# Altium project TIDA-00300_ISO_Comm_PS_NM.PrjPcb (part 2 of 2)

## Sheet TIDA-00300_ISO_Comm_PS_NM_Pg6.SchDoc
size 431 x 279 mm; Date: Not shown in title block; ApprovedBy: Not shown in title block; CheckedBy: Not shown in title block; Author: Not shown in title block; CompanyName: Not shown in title block; DrawnBy: Sreenivasa; Engineer: Not shown in title block; Organization: Not shown in title block; Address1: Not shown in title block; Address2: Not shown in title block; Address3: Not shown in title block; Address4: Not shown in title block; DocumentNumber: 1; Revision: Use project parameter SCH_Rev; SheetNumber: 6; SheetTotal: 7; PageSetup: Record=PageOptions¦CenterHorizontal=True¦CenterVertical=True¦PrintScale=0.62¦XCorrection=1.00¦YCorrection=1.00¦PrintKind=0¦BorderSize=5000000¦LeftOffset=0¦BottomOffset=0¦Orientation=2¦PaperLength=1000¦PaperWidth=1000¦Scale=100¦PaperSource=15¦PrintQuality=600¦MediaType=1¦DitherType=10¦PrintScaleMode=1¦PaperKind=Letter
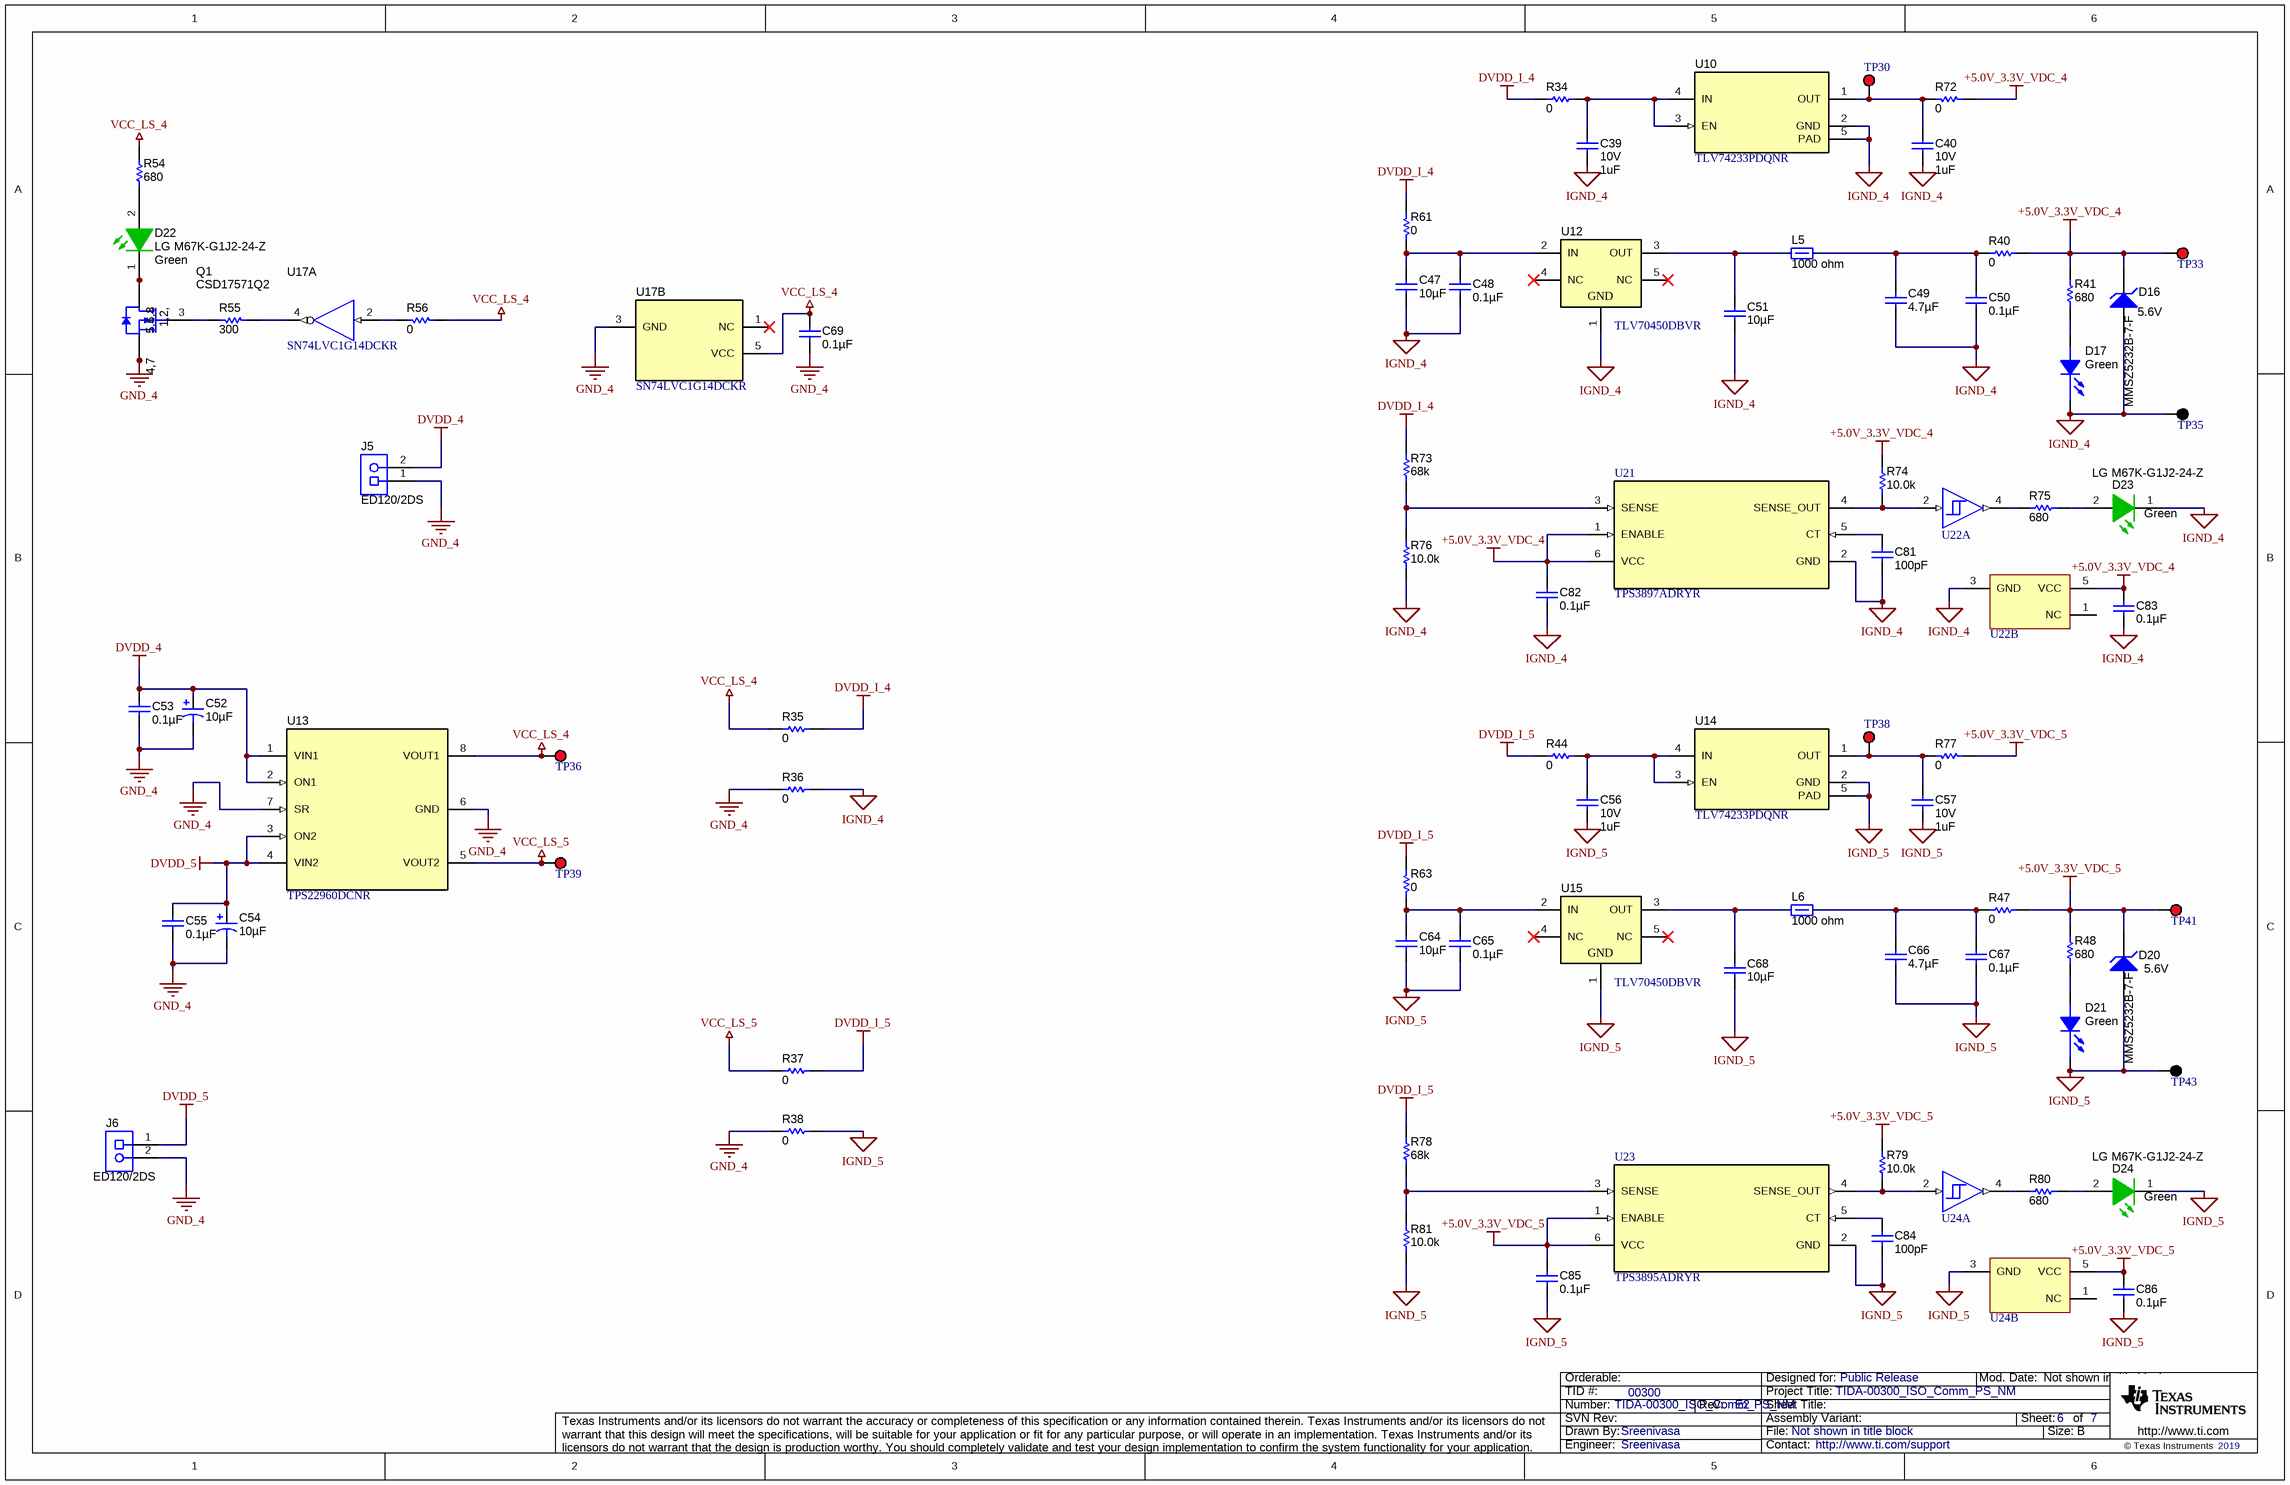
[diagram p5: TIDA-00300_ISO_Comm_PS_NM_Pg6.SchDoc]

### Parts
C39  VDC_V: 10V  ValueDisplayed: 1uF  [0402]  (hidden comment: GRM155R61A105KE15D)
C40  VDC_V: 10V  ValueDisplayed: 1uF  [0402]  (hidden comment: GRM155R61A105KE15D)
C47  ValueDisplayed: 10µF  [1210]
C48  ValueDisplayed: 0.1µF  [0603]
C49  ValueDisplayed: 4.7µF  [0805_HV]
C50  ValueDisplayed: 0.1µF  [0603]
C51  ValueDisplayed: 10µF  [1210]
C52  ValueDisplayed: 10µF  [3528-21]  (hidden comment: T491B106K016AT)
C53  ValueDisplayed: 0.1µF  [0603]
C54  ValueDisplayed: 10µF  [3528-21]  (hidden comment: T491B106K016AT)
C55  ValueDisplayed: 0.1µF  [0603]
C56  VDC_V: 10V  ValueDisplayed: 1uF  [0402]  (hidden comment: GRM155R61A105KE15D)
C57  VDC_V: 10V  ValueDisplayed: 1uF  [0402]  (hidden comment: GRM155R61A105KE15D)
C64  ValueDisplayed: 10µF  [1210]
C65  ValueDisplayed: 0.1µF  [0603]
C66  ValueDisplayed: 4.7µF  [0805_HV]
C67  ValueDisplayed: 0.1µF  [0603]
C68  ValueDisplayed: 10µF  [1210]
C69  ValueDisplayed: 0.1µF  [0603]  (hidden comment: GMK107BJ104KAHT)
C81  ValueDisplayed: 100pF  [0402]  (hidden comment: 0402YC101KAT2A)
C82  ValueDisplayed: 0.1µF  [0603]
C83  ValueDisplayed: 0.1µF  [0603]
C84  ValueDisplayed: 100pF  [0402]  (hidden comment: 0402YC101KAT2A)
C85  ValueDisplayed: 0.1µF  [0603]
C86  ValueDisplayed: 0.1µF  [0603]
D16  MMSZ5232B-7-F  value 5.6V  [SOD-123]
D17  value Green  [LED0603AA]
D20  MMSZ5232B-7-F  value 5.6V  [SOD-123]
D21  value Green  [LED0603AA]
D22  LG M67K-G1J2-24-Z  value Green  [LG_M67K_Green]
D23  LG M67K-G1J2-24-Z  value Green  [LG_M67K_Green]
D24  LG M67K-G1J2-24-Z  value Green  [LG_M67K_Green]
J5  ED120/2DS  [CONN_ED120-2DS]
J6  ED120/2DS  [CONN_ED120-2DS]
L5  value 1000 ohm  [MMZ1608_095]  (hidden comment: MMZ1608B102CTA00)
L6  value 1000 ohm  [MMZ1608_095]  (hidden comment: MMZ1608B102CTA00)
Q1  CSD17571Q2  [DQK0006C]
R34  ValueDisplayed: 0  [0402S]  (hidden comment: RC0402JR-070RL)
R35  ValueDisplayed: 0  [0603]  (hidden comment: CRCW06030000Z0EA)
R36  ValueDisplayed: 0  [0603]  (hidden comment: CRCW06030000Z0EA)
R37  ValueDisplayed: 0  [0603]  (hidden comment: CRCW06030000Z0EA)
R38  ValueDisplayed: 0  [0603]  (hidden comment: CRCW06030000Z0EA)
R40  value 0  [0603]  (hidden comment: CRCW06030000Z0EA)
R41  ValueDisplayed: 680  [0603]  (hidden comment: RC0603FR-07680RL)
R44  ValueDisplayed: 0  [0402S]  (hidden comment: RC0402JR-070RL)
R47  value 0  [0603]  (hidden comment: CRCW06030000Z0EA)
R48  ValueDisplayed: 680  [0603]  (hidden comment: RC0603FR-07680RL)
R54  ValueDisplayed: 680  [0603]  (hidden comment: RC0603FR-07680RL)
R55  ValueDisplayed: 300  [0603]  (hidden comment: CRCW0603300RJNEA)
R56  ValueDisplayed: 0  [0603]  (hidden comment: RMCF0603ZT0R00)
R61  ValueDisplayed: 0  [0603]  (hidden comment: CRCW06030000Z0EA)
R63  ValueDisplayed: 0  [0603]  (hidden comment: CRCW06030000Z0EA)
R72  ValueDisplayed: 0  [0603]  (hidden comment: CRCW06030000Z0EA)
R73  ValueDisplayed: 68k  [0402]  (hidden comment: CRCW040268K0JNED)
R74  ValueDisplayed: 10.0k  [0402]  (hidden comment: CRCW040210K0FKED)
R75  ValueDisplayed: 680  [0603]  (hidden comment: RC0603FR-07680RL)
R76  ValueDisplayed: 10.0k  [0402]  (hidden comment: CRCW040210K0FKED)
R77  ValueDisplayed: 0  [0603]  (hidden comment: CRCW06030000Z0EA)
R78  ValueDisplayed: 68k  [0402]  (hidden comment: CRCW040268K0JNED)
R79  ValueDisplayed: 10.0k  [0402]  (hidden comment: CRCW040210K0FKED)
R80  ValueDisplayed: 680  [0603]  (hidden comment: RC0603FR-07680RL)
R81  ValueDisplayed: 10.0k  [0402]  (hidden comment: CRCW040210K0FKED)
TP30  5000  [Keystone5000]  (value not drawn)
TP33  5000  [Keystone5000]  (value not drawn)
TP35  5001  [Keystone5001]  (value not drawn)
TP36  5000  [Keystone5000]  (value not drawn)
TP38  5000  [Keystone5000]  (value not drawn)
TP39  5000  [Keystone5000]  (value not drawn)
TP41  5000  [Keystone5000]  (value not drawn)
TP43  5001  [Keystone5001]  (value not drawn)
U10  TLV74233PDQNR  [DQN0004A]
U12  TLV70450DBVR  [DBV0005A_N]
U13  TPS22960DCNR  [DCN0008A_N]
U14  TLV74233PDQNR  [DQN0004A]
U15  TLV70450DBVR  [DBV0005A_N]
U17  SN74LVC1G14DCKR  [DCK0005A_N]  (parts A,B of 2)
U21  TPS3897ADRYR  [DRY0006A]
U22  SN74LVC1G17DCKR  [DCK0005A_N]  (value not drawn)  (parts A,B of 2)
U23  TPS3895ADRYR  [DRY0006A]
U24  SN74LVC1G17DCKR  [DCK0005A_N]  (value not drawn)  (parts A,B of 2)

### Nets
+5.0V_3.3V_VDC_4: C82.1 C83.1 D16.1(K) R40.2 R41.2 R72.1 R74.1 TP33.1 U21.1(ENABLE) U21.6(VCC) U22.5(VCC)
+5.0V_3.3V_VDC_5: C85.1 C86.1 D20.1(K) R47.2 R48.2 R77.1 R79.1 TP41.1 U23.1(ENABLE) U23.6(VCC) U24.5(VCC)
DVDD_4: C52.1(+) C53.2 J5.2 U13.1(VIN1) U13.2(ON1)
DVDD_5: C54.1(+) C55.2 J6.1 U13.3(ON2) U13.4(VIN2)
DVDD_I_4: R34.1 R35.1 R61.2 R73.2
DVDD_I_5: R37.1 R44.1 R63.2 R78.2
GND_4: C52.2(-) C53.1 C54.2(-) C55.1 C69.2 J5.1 J6.2 Q1.4(S) Q1.7(S) R36.2 R38.2 U13.6(GND) U13.7(SR) U17.3(GND)
IGND_4: C39.2 C40.2 C47.1 C48.2 C49.1 C50.2 C51.1 C81.2 C82.2 C83.2 D16.2(A) D17.1(C) D23.1(K) R36.1 R76.1 TP35.1 U10.2(GND) U10.5(PAD) U12.1(GND) U21.2(GND) U22.3(GND)
IGND_5: C56.2 C57.2 C64.1 C65.2 C66.1 C67.2 C68.1 C84.2 C85.2 C86.2 D20.2(A) D21.1(C) D24.1(K) R38.1 R81.1 TP43.1 U14.2(GND) U14.5(PAD) U15.1(GND) U23.2(GND) U24.3(GND)
VCC_LS_4: C69.1 R35.2 R54.2 R56.1 TP36.1 U13.8(VOUT1) U17.5(VCC)
VCC_LS_5: R37.2 TP39.1 U13.5(VOUT2)
NetC39_1: C39.1 R34.2 U10.3(EN) U10.4(IN)
NetC40_1: C40.1 R72.2 TP30.1 U10.1(OUT)
NetC47_2: C47.2 C48.1 R61.1 U12.2(IN)
NetC49_2: C49.2 C50.1 L5.2 R40.1
NetC51_2: C51.2 L5.1 U12.3(OUT)
NetC56_1: C56.1 R44.2 U14.3(EN) U14.4(IN)
NetC57_1: C57.1 R77.2 TP38.1 U14.1(OUT)
NetC64_2: C64.2 C65.1 R63.1 U15.2(IN)
NetC66_2: C66.2 C67.1 L6.2 R47.1
NetC68_2: C68.2 L6.1 U15.3(OUT)
NetC81_1: C81.1 U21.5(CT)
NetC84_1: C84.1 U23.5(CT)
NetD17_2: D17.2(A) R41.1
NetD21_2: D21.2(A) R48.1
NetD22_1: D22.1(K) Q1.1(D) Q1.2(D) Q1.5(D) Q1.6(D) Q1.8(D)
NetD22_2: D22.2(A) R54.1
NetD23_2: D23.2(A) R75.2
NetD24_2: D24.2(A) R80.2
NetQ1_3: Q1.3(G) R55.1
NetR55_2: R55.2 U17.4(Y)
NetR56_2: R56.2 U17.2(A)
NetR73_1: R73.1 R76.2 U21.3(SENSE)
NetR74_2: R74.2 U21.4(SENSE_OUT) U22.2(A)
NetR75_1: R75.1 U22.4(Y)
NetR78_1: R78.1 R81.2 U23.3(SENSE)
NetR79_2: R79.2 U23.4(SENSE_OUT) U24.2(A)
NetR80_1: R80.1 U24.4(Y)

Not connected (* = marked no-connect by the designer): U12 4(NC)* 5(NC)*; U15 4(NC)* 5(NC)*; U17 1(NC)*; U22 1(NC); U24 1(NC)

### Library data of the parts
C39 C40 C56 C57 = CMP-0006563-2: CAP, CERM, 1 uF, 10 V, +/- 10%, X5R, 0402; Manufacturer: MuRata; TaMin_C: -55°C; Polarized: N; SizeAreaWB_mm2: 3; Value1: Unknown; U/M: EA; Value: 1uF; TaMax_C: 85°C; SizeZ_mm: 0.6; SizeX_mm: 1; SizeY_mm: 0.5; Cap_F: 1µF; AEC Category: Q200
C47 C51 C64 C68 = GMK325AB7106MM-T: CAP, CERM, 10uF, 35V, +/-20%, X7R, 1210; Manufacturer: Taiyo Yuden; Polarized: N; CompType: Capacitor; U/M: EA; Cap_F: 0.00001; Tolerance_%: 20; Value1: Unknown; VDC_V: 35; TaMin_C: -55; TaMax_C: 125
C48 C50 C53 C55 C65 C67 C82 C83 C85 C86 = C0603C104K5RACTU: CAP, CERM, 0.1uF, 50V, +/-10%, X7R, 0603; Manufacturer: Kemet; Polarized: N; CompType: Capacitor; U/M: EA; Cap_F: 0.0000001; Tolerance_%: 10; Value1: Unknown; VDC_V: 50; TaMin_C: -55; TaMax_C: 125
C49 C66 = C2012X5R1H475K125AB: 4.7µF ±10% 50V X5R Ceramic Capacitor -55°C ~ 85°C; PartNumber: GRM21BR61H475KE51L; Manufacturer: TDK; Polarized: N; Value: 4.7uF; U/M: EA; Cap_F: 0.0000047; Tolerance_%: 10; Value1: Unknown; VDC_V: 50; TaMin_C: -55; TaMax_C: 85; Cap_Case: 0805
C52 C54 = 293D106X9016B2TE3: CAP, TA, 10 µF, 16 V, +/- 10%, 2 ohm, SMD; Manufacturer: Vishay-Sprague; Polarized: Y; CompType: Capacitor; Value: 10uF; U/M: EA; Cap_F: 0.00001; Tolerance_%: 10; Value1: 2 ohm; VDC_V: 16; Value2: 16V; ESR_ohm: 2; IRMS_A: 0.21; TaMin_C: -55; TaMax_C: 125; Cap_Case: B
C69 = 06033C104JAT2A: 0.1µF ±10% 35V Ceramic Capacitor X5R 0603; Manufacturer: Taiyo Yuden; Polarized: N; Value: 0.1uF; U/M: EA; Cap_F: 0.0000001; Tolerance_%: 5; ESR_ohm: 0.05; Value1: 0.05 ohm; VDC_V: 25; Value2: 25V; TempCo: X7R; TaMin_C: -55; TaMax_C: 125; SizeArea_mm2: 1.28; SizeAreaWB_mm2: 4.68; SizeX_mm: 1.6; SizeY_mm: 0.8; SizeZ_mm: 1; AEC Category: Q200
C81 C84 = 0402YC101KAT2A: CAP, CERM, 100 pF, 16 V,+/- 10%, X7R, 0402; Manufacturer: AVX; Polarized: N; CompType: Capacitor; Value: 100pF; U/M: EA; Cap_F: 0.0000000001; Tolerance_%: 10; VDC_V: 16; Value2: 16V; TaMin_C: -55; TaMax_C: 125; SizeArea_mm2: 0.5; SizeAreaWB_mm2: 3; SizeX_mm: 1; SizeZ_mm: 0.6; AEC Category: Q200
D16 D20 = MMSZ5232B-7-F: Diode, Zener, 5.6 V, 500 mW, SOD-123; Manufacturer: Diodes Inc.; SymbolCreator: a0412235; U/M: EA; Power_W: 0.5; Vz_V: 5.6; Value1: 0.5W; RJA_CperW: 350; AEC Category: Q101
D17 D21 = LED_LG L29K-G2J1-24-Z: LED SmartLED Green 570NM; Manufacturer: OSRAM; SymbolCreator: x0120606
D22-D24 = LG M67K-G1J2-24-Z: LED, Green, SMD; Manufacturer: OSRAM; SymbolCreator: Altium; Type: AlInGaP; Vf_V: 1.8; Value2: 1.8V; Io_A: 0.002; Vr_V: 12; Tjmax_C: 125; Value1: W; Angle: 120; U/M: EA
J5 J6 = ED120/2DS: TERMINAL BLOCK 5.08MM VERT 2POS, TH; Manufacturer: On-Shore Technology; SymbolCreator: a0412235; U/M: EA
L5 L6 = MMZ1608B102CTA00: Ferrite Bead, 1000 ohm @ 100 MHz, 0.3 A, 0603; Manufacturer: TDK; Imax_A: 0.3; DCR_ohm: 0.6; Value1: 0.6 ohm; Value2: 0.3A; ZTyp@100MHz_Ohm: 1000
Q1 = CSD17571Q2: MOSFET, N-CH, 30 V, 22 A, DQK0006C (WSON-6); Manufacturer: Texas Instruments; Alternate Manufacturer: None; U/M: EA; ChType: N; Value: 30V; VdsMax_V: 30; Value1: 0.029 ohm; Rdson45_ohm: 0.029; Value2: 2.4 nC; QgTyp_nC: 2.4; Vgs_V: 20; IdsMax_A: 22; SizeAreaWB_mm2: 9; SizeArea_mm2: 4; SizeX_mm: 2; SizeZ_mm: 0.8; AEC Category: Q101
R34 R44 = CMP-0027004-2: RES, 0, 5%, 0.063 W, 0402; Manufacturer: Yageo America; Power_W: 63mW; TempCo: 200 ppm/C; Value_Code: 0000; U/M: EA; Value: 0; EIA_Code: E24; SizeX_mm: 1; SizeY_mm: 0.5; SizeZ_mm: 0.6; Value2: 0.063W; VDC_V: 50V; AEC Category: Q200
R35-R38 R61 R63 R72 R77 = CRCW06030000Z0EA: RES, 0, 5%, 0.1 W, 0603; Manufacturer: Vishay-Dale; CompType: Resistor; Value: 0; Value_Code: 0000; Tolerance_%: 5; Power_W: 0.1; Value2: 0.1W; VDC_V: 75; TempCo: 200 ppm/C; EIA_Code: E24; U/M: EA
R40 R47 = CRCW06030000Z0EA: RES, 0 ohm, 5%, 0.1W, 0603; Manufacturer: Vishay-Dale; CompType: Resistor; Value_Code: 0000; Tolerance_%: 5; Power_W: 0.1; VDC_V: 75; TempCo: 200 ppm/C; EIA_Code: E24; U/M: EA
R41 R48 R54 R75 R80 = RC0603FR-07680RL: RES, 680, 1%, 0.1 W, 0603; Manufacturer: Yageo America; CompType: Resistor; Value: 680; Value_Code: 680R; Tolerance_%: 1; Power_W: 0.1; Value2: 0.1W; VDC_V: 150; TempCo: 200 ppm/C; SizeArea_mm2: 1.28; SizeX_mm: 1.6; SizeY_mm: 0.8; U/M: EA; AEC Category: Q200; Green_Lifecycle: Active; Green_REACh: Passed
R55 = CRCW0603300RJNEA: RES, 300, 5%, 0.1 W, 0603; Manufacturer: Vishay-Dale; CompType: Resistor; Value: 300; Value_Code: 300R; Tolerance_%: 5; Power_W: 0.1; Value2: 0.1W; VDC_V: 75; TempCo: 200 ppm/C; SizeArea_mm2: 1.28; SizeX_mm: 1.6; SizeY_mm: 0.8; SizeZ_mm: 1; EIA_Code: E24; U/M: EA; AEC Category: Q200
R56 = RMCF0603ZT0R00: RES, 0, 1%, 0.1 W, AEC-Q200 Grade 0, 0603; Manufacturer: Stackpole Electronics Inc; CompType: Resistor; Value: 0; Tolerance_%: 1; Power_W: 0.1; Value2: 0.1W; TempCo: ppm/C; SizeArea_mm2: 1.28; SizeX_mm: 1.6; SizeY_mm: 0.8; U/M: EA; AEC Category: Q200; AEC Qualified: Y
R73 R78 = CRCW040268K0JNED: RES, 68 k, 5%, 0.063 W, 0402; Manufacturer: Vishay-Dale; CompType: Resistor; Value: 68k; Res_ohm: 68000; Value_Code: 68k0; Tolerance_%: 5; Power_W: 0.063; Value2: 0.063W; VDC_V: 50; TempCo: 200 ppm/C; SizeArea_mm2: 0.5; SizeX_mm: 1; SizeZ_mm: 0.6; EIA_Code: E24; U/M: EA; AEC Category: Q200
R74 R76 R79 R81 = CRCW040210K0FKED: RES, 10.0 k, 1%, 0.063 W, 0402; Manufacturer: Vishay-Dale; CompType: Resistor; Value: 10.0k; Res_ohm: 10000; Value_Code: 10k0; Tolerance_%: 1; Power_W: 0.063; Value2: 0.063W; VDC_V: 50; TempCo: 100 ppm/C; SizeArea_mm2: 0.5; SizeZ_mm: 0.6; EIA_Code: E96; U/M: EA; AEC Category: Q200; Green_Lifecycle: Active; Green_REACh: Passed
TP30 TP33 TP36 TP38 TP39 TP41 = 5000: Test Point, Miniature, Red, TH; Manufacturer: Keystone; CompType: Test Point Loop; ContactFinish: Silver; Green_Lifecycle: Active; Green_REACh: Passed
TP35 TP43 = 5001: Test Point, Miniature, Black, TH; Manufacturer: Keystone; CompType: Test Point Loop; ContactFinish: Silver; Green_Lifecycle: Active; Green_REACh: Passed
U10 U14 = CMP-0079101-1: 200-mA, Small Size, Low-Dropout Linear Voltage Regulator, DQN0004A (X2SON-4); Alternate Manufacturer: Texas Instruments; SizeAreaWB_mm2: 4; SizeZ_mm: 0.4; SizeX_mm: 1; CompType: IC; AEC Qualified: N; AEC Category: Q200
U12 U15 = TLV70450DBVR: Single Output LDO, 150 mA, Fixed 5 V Output, 2.5 to 24 V Input, with Ultra-Low IQ, 5-pin SOT-23 (DBV), -40 to 125 degC, Green (RoHS & no Sb/Br); Manufacturer: Texas Instruments; Alternate PartNumber: Equivalent; Accuracy(%): 2; Fixed Output Options(V): 5; Iout(Max)(A): 0.15; Iq(Typ)(mA): 0.003; SubFamily: Single Channel LDO; Vdo(Typ)(mV): 400; Vin(Max)(V): 24; Vin(Min)(V): 2.5
U13 = CMP-0066654-1: 5.5V, 0.5A, 435mΩ, 2-Channel Load Switch with Quick Output Discharge, DCN0008A (SOT-23-8); Alternate Manufacturer: Texas Instruments; SizeAreaWB_mm2: 15.21; U/M: EA; SizeZ_mm: 1.1; SizeX_mm: 2.9; SizeArea_mm2: 8.41; CompType: IC
U17 = CMP-0051641-4: Single Schmitt-Trigger Inverter, DCK0005A (SOT-SC70-5); Manufacturer: Texas Instruments; Alternate PartNumber: SN74LVC1G14DCKT; Output Drive (IOL/IOH)(Max)(mA): 32/-32; Schmitt Trigger: Yes; Logic: Inverting; Bits(#): 1; Rating: Catalog; tpd @ Nom Voltage(Max)(ns): 11,6.5,5.5,5; Voltage(Nom)(V): 1.8,2.5,3.3,5; Output Type: CMOS; VCC(Min)(V): 1.65; ICC @ Nom Voltage(Max)(mA): 0.01; Input Type: CMOS/TTL; F @ Nom Voltage(Max)(Mhz): 150; VCC(Max)(V): 5.5; 3-State Output: No; AEC Category: Q200; AEC Qualified: N; CompType: IC; Green_Lifecycle: Active; Green_REACh: Passed; SizeAreaWB_mm2: 9.3; SizeArea_mm2: 4.2; SizeX_mm: 2.1; SizeY_mm: 2.0; SizeZ_mm: 1.1
U21 = CMP-0032427-1: Single Channel, Ultra Small, Adjustable Supervisory Circuit with Active-High, Open-Drain Output, 1 Supply Monitored, -40 to 125 degC, 6-pin SON (DRY), Green (RoHS & no Sb/Br); Manufacturer: Texas Instruments; Iq(Typ)(uA): 6; SubFamily: Supervisor and Reset IC; Time Delay(ms): 0.04, Programmable; VCC(Min)(V): 1.7; Reset Threshold Accuracy(%): 0.25; Enable Pin: TRUE; # of Supplies Monitored: 1; Rating: Catalog; VCC(Max)(V): 6.5
U22 U24 = CMP-0051704-1: Single Schmitt-Trigger Buffer, DCK0005A, LARGE T&R; Manufacturer: Texas Instruments; tpd @ Nom Voltage(Max)(ns): 11,6.5,5.5,5; Bits(#): 1; VCC(Min)(V): 1.65; F @ Nom Voltage(Max)(Mhz): 150; VCC(Max)(V): 5.5; Input Type: CMOS/TTL; Sub-Family: Non-Inverting Buffer/Driver; Output Type: CMOS; Output Drive (IOL/IOH)(Max)(mA): 32/-32; 3-State Output: No; Logic: True; ICC @ Nom Voltage(Max)(mA): 0.01; Voltage(Nom)(V): 1.8,2.5,3.3,5; Rating: Catalog; Schmitt Trigger: Yes; Technology Family: LVC
U23 = CMP-0032419-1: Single Channel, Ultra Small, Adjustable Supervisory Circuit with Active-High, Push-Pull Output, 1 Supply Monitored, -40 to 125 degC, 6-pin SON (DRY), Green (RoHS & no Sb/Br); Manufacturer: Texas Instruments; Reset Threshold Accuracy(%): 0.25; VCC(Max)(V): 6.5; Rating: Catalog; Time Delay(ms): 0.04, Programmable; VCC(Min)(V): 1.7; Enable Pin: TRUE; # of Supplies Monitored: 1; SubFamily: Supervisor and Reset IC; Iq(Typ)(uA): 6

## Sheet TIDA-00300_ISO_Comm_PS_NM_EVM_Hardware_Pg7.SchDoc: Hardware
size 431 x 279 mm; Date: Not shown in title block; ApprovedBy: Not shown in title block; CheckedBy: Not shown in title block; Author: Not shown in title block; CompanyName: Not shown in title block; DrawnBy: Sreenivasa; Engineer: Not shown in title block; Organization: Not shown in title block; Address1: Not shown in title block; Address2: Not shown in title block; Address3: Not shown in title block; Address4: Not shown in title block; DocumentNumber: 1; Revision: Use project parameter SCH_Rev; SheetNumber: 7; SheetTotal: 7; PageSetup: Record=PageOptions¦CenterHorizontal=True¦CenterVertical=True¦PrintScale=1.00¦XCorrection=1.00¦YCorrection=1.00¦PrintKind=0¦BorderSize=5000000¦LeftOffset=0¦BottomOffset=0¦Orientation=2¦PaperLength=1000¦PaperWidth=1000¦Scale=100¦PaperSource=15¦PrintQuality=600¦MediaType=1¦DitherType=10¦PaperKind=Letter¦PrintScaleMode=1
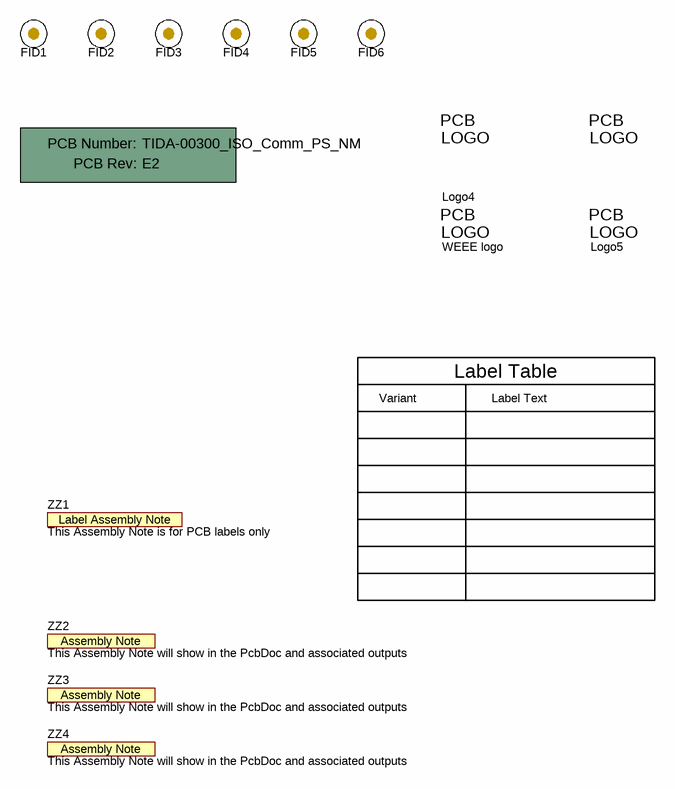
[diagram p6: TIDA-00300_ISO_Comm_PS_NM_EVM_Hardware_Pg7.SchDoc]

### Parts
!PCB1  Printed Circuit Board  (value not drawn)  (mechanical)
FID1  Fiducial  [Fiducial10-30]  (value not drawn)
FID2  Fiducial  [Fiducial10-30]  (value not drawn)
FID3  Fiducial  [Fiducial10-30]  (value not drawn)
FID4  Fiducial  [Fiducial10-30]  (value not drawn)
FID5  Fiducial  [Fiducial10-30]  (value not drawn)
FID6  Fiducial  [Fiducial10-30]  (value not drawn)
Logo2  Pb-Free Symbol  [Pb-Free_Overlay_Small]  (value not drawn)  (no BOM)
Logo3  FCC disclaimer  [FCC_disclaimer]  (value not drawn)  (no BOM)
Logo4  WEEE logo  [WEEE_Minimum]  (no BOM)
Logo5  ESD Susceptible  [ESD_Overlay_small]  (value not drawn)  (no BOM)
ZZ1  This Assembly Note is for PCB labels only  [AssemblyNoteLabel]  (no BOM)
ZZ2  This Assembly Note will show in the PcbDoc and associated outputs  [AssemblyNote]  (no BOM)
ZZ3  This Assembly Note will show in the PcbDoc and associated outputs  [AssemblyNote]  (no BOM)
ZZ4  This Assembly Note will show in the PcbDoc and associated outputs  [AssemblyNote]  (no BOM)

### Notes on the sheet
- Variant
- Label Table
- Label Text

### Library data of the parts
!PCB1 = PCB: Manufacturer: Any; PartNumber: TIDA-00300_ISO_Comm_PS_NM; SymbolCreator: a0412235
FID1-FID6 = Fiducial: Fiducial mark.  There is nothing to buy or mount.; SymbolCreator: codlsc
Logo2 = Pb-Free: SymbolCreator: a0412235
Logo3 = FCC_disclaimer: SymbolCreator: a0412235
Logo4 = CMP-0074769-1
Logo5 = ESD_Susceptible: ESD Susceptible Symbol; SymbolCreator: a0412235
ZZ1 = AssemblyNoteLabel: SymbolCreator: a0412235
ZZ2-ZZ4 = AssemblyNote: SymbolCreator: codlsc

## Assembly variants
001: not fitted R8 R22 R29 R42 R52 R57 R62 R64 R72 R77 R95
